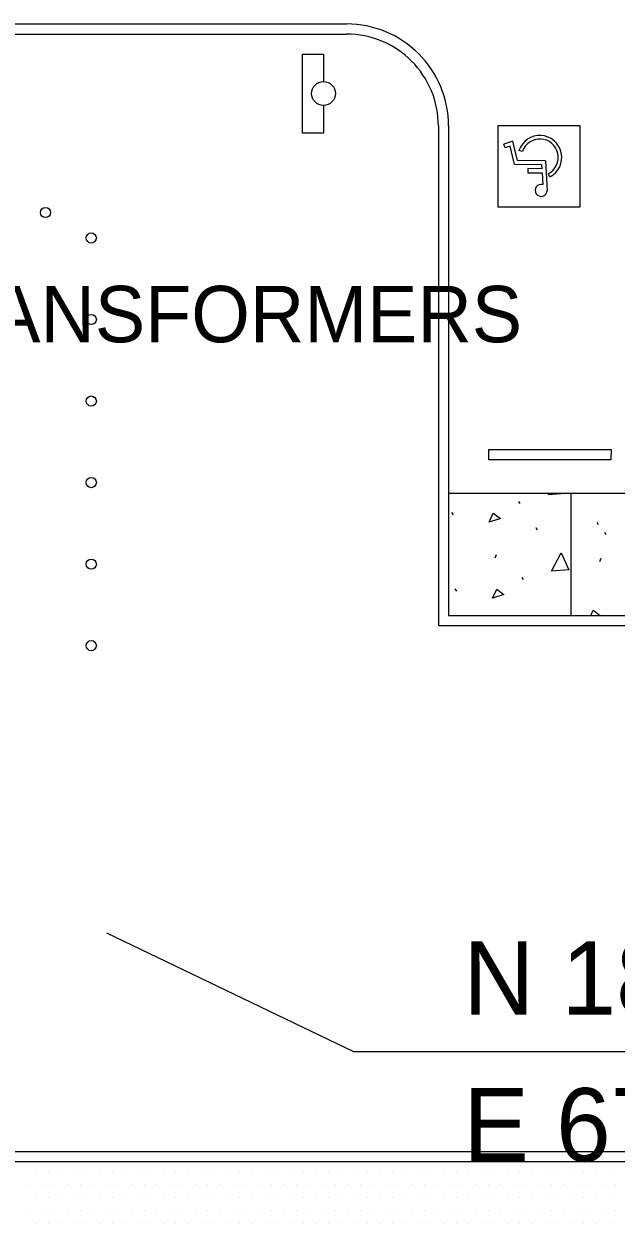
# Model space of a CAD drawing. Extents: x 6712138 to 6712574, y 1869536 to 1870160.
# Drawn here: x 6712356.5 to 6712385.6, y 1869836.3 to 1869895.1 of the extents above; entities that cross this region are included whole.
import ezdxf

# ---------------------------------------------------------------- set-up
doc = ezdxf.new("R2010")
doc.units = 0
for name, color, linetype in [('A-ANNO-TEXT', 7, 'Continuous'), ('A-FLOR-OTLN', 7, 'Continuous'), ('A-FLOR-PATT', 7, 'Continuous'), ('C-PRKG-CONC', 7, 'Continuous'), ('C-SIGN-PARKING', 7, 'Continuous'), ('I-FURN', 7, 'Continuous'), ('I-WALL', 7, 'Continuous'), ('L-SITE-PAVE', 7, 'Continuous')]:
    doc.layers.add(name, color=color, linetype=linetype)

# ---------------------------------------------------------------- blocks, each defined once
blk = doc.blocks.new('G-handy2')
for p, q in [((0, 0), (-0.0002239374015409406, 0.0035868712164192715)), ((-0.000552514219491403, 0.001912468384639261), (-0.0003555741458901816, 0.001537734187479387)), ((0.000380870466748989, 0.0014482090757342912), (0.0002942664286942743, 0.002835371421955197)), ((0.0020983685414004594, 0.0014486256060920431), (0.000380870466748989, 0.0014482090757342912)), ((0.0020984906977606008, 0.0009449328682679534), (0.0020983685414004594, 0.0014486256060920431)), ((0, 0), (0.0033054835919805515, 8.016511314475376e-07)), ((0.0004123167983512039, 0.0009445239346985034), (0.0020984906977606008, 0.0009449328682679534)), ((0.0004419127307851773, 0.0004704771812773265), (0.0004123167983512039, 0.0009445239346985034)), ((0.0004419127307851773, 0.0004704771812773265), (0.0036734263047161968, 0.00047126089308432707)), ((0.0033054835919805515, 8.016511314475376e-07), (0.0038831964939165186, -0.0023286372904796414)), ((0.0036734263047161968, 0.00047126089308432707), (0.004214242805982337, -0.0017094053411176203)), ((0.002744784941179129, -0.0010810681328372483), (0.00314717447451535, -0.0012125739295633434)), ((0.0038831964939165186, -0.0023286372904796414), (0.004932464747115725, -0.0019506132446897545)), ((0.004214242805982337, -0.0017094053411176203), (0.004773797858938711, -0.0015078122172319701)), ((0.004773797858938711, -0.0015078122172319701), (0.004932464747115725, -0.0019506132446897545))]:
    blk.add_line(p, q)
for centre, radius, start, end in [((0.000485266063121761, 0.0035214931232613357), 0.0007122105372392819, 254.44408755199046, 174.7330607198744), ((0.0006632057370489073, -0.0004007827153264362), 0.0026132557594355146, 117.72399317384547, 341.90197805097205), ((0.0006632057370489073, -0.0004007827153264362), 0.002189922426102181, 117.72399317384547, 341.90197805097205)]:
    blk.add_arc(centre, radius, start, end)

msp = doc.modelspace()

# ---------------------------------------------------------------- linework, layer by layer
at = {"layer": 'A-FLOR-OTLN'}
for points in [[(6712251.18275902, 1869839.7810671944), (6712251.18275902, 1869722.3227338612), (6712419.140073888, 1869722.3227338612), (6712419.140073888, 1869718.864400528), (6712468.641092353, 1869718.864400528), (6712468.641092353, 1869839.7810671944)], [(6712251.68275902, 1869839.2810671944), (6712251.68275902, 1869722.8227338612), (6712419.640073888, 1869722.8227338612), (6712419.640073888, 1869719.364400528), (6712468.141092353, 1869719.364400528), (6712468.141092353, 1869839.2810671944)]]:
    msp.add_lwpolyline(points, close=True, dxfattribs=at)
at = {"layer": 'A-FLOR-PATT'}
for p, q in [((6712380.767264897, 1869871.685944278), (6712380.833931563, 1869871.5792776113)), ((6712377.487264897, 1869871.1326109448), (6712377.56059823, 1869871.025944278)), ((6712381.6205982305, 1869870.3992776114), (6712381.693931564, 1869870.2926109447)), ((6712384.607264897, 1869870.6726109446), (6712384.68059823, 1869870.5592776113)), ((6712384.987264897, 1869870.1726109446), (6712385.06059823, 1869870.0659442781)), ((6712379.6205982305, 1869868.9126109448), (6712379.687264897, 1869869.0726109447)), ((6712384.753931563, 1869868.7326109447), (6712384.820598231, 1869868.8926109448)), ((6712377.653931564, 1869867.3926109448), (6712377.727264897, 1869867.2859442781)), ((6712380.933931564, 1869867.945944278), (6712381.007264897, 1869867.845944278)), ((6712357.086960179, 1869838.781746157), (6712357.086960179, 1869838.781746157)), ((6712357.711960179, 1869838.781746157), (6712357.711960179, 1869838.781746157)), ((6712358.336960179, 1869838.781746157), (6712358.336960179, 1869838.781746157)), ((6712358.961960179, 1869838.781746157), (6712358.961960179, 1869838.781746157)), ((6712359.586960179, 1869838.781746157), (6712359.586960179, 1869838.781746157)), ((6712360.211960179, 1869838.781746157), (6712360.211960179, 1869838.781746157)), ((6712360.836960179, 1869838.781746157), (6712360.836960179, 1869838.781746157)), ((6712361.461960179, 1869838.781746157), (6712361.461960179, 1869838.781746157)), ((6712362.086960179, 1869838.781746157), (6712362.086960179, 1869838.781746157)), ((6712362.711960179, 1869838.781746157), (6712362.711960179, 1869838.781746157)), ((6712363.336960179, 1869838.781746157), (6712363.336960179, 1869838.781746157)), ((6712363.961960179, 1869838.781746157), (6712363.961960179, 1869838.781746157)), ((6712364.586960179, 1869838.781746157), (6712364.586960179, 1869838.781746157)), ((6712365.211960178, 1869838.781746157), (6712365.211960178, 1869838.781746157)), ((6712365.836960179, 1869838.781746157), (6712365.836960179, 1869838.781746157)), ((6712366.461960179, 1869838.781746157), (6712366.461960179, 1869838.781746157)), ((6712367.086960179, 1869838.7817461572), (6712367.086960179, 1869838.7817461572)), ((6712367.711960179, 1869838.7817461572), (6712367.711960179, 1869838.7817461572)), ((6712368.336960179, 1869838.781746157), (6712368.336960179, 1869838.781746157)), ((6712368.961960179, 1869838.781746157), (6712368.961960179, 1869838.781746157)), ((6712369.586960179, 1869838.781746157), (6712369.586960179, 1869838.781746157)), ((6712370.211960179, 1869838.781746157), (6712370.211960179, 1869838.781746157)), ((6712370.836960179, 1869838.781746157), (6712370.836960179, 1869838.781746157)), ((6712371.461960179, 1869838.781746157), (6712371.461960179, 1869838.781746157)), ((6712372.086960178, 1869838.781746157), (6712372.086960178, 1869838.781746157)), ((6712372.711960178, 1869838.781746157), (6712372.711960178, 1869838.781746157)), ((6712373.336960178, 1869838.781746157), (6712373.336960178, 1869838.781746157)), ((6712373.961960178, 1869838.781746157), (6712373.961960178, 1869838.781746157)), ((6712374.586960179, 1869838.7817461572), (6712374.586960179, 1869838.7817461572)), ((6712375.211960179, 1869838.781746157), (6712375.211960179, 1869838.781746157)), ((6712375.836960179, 1869838.781746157), (6712375.836960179, 1869838.781746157)), ((6712376.461960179, 1869838.781746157), (6712376.461960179, 1869838.781746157)), ((6712377.086960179, 1869838.781746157), (6712377.086960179, 1869838.781746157)), ((6712377.711960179, 1869838.781746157), (6712377.711960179, 1869838.781746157)), ((6712378.336960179, 1869838.781746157), (6712378.336960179, 1869838.781746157)), ((6712378.961960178, 1869838.781746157), (6712378.961960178, 1869838.781746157)), ((6712379.586960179, 1869838.781746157), (6712379.586960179, 1869838.781746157)), ((6712380.211960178, 1869838.781746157), (6712380.211960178, 1869838.781746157)), ((6712380.836960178, 1869838.781746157), (6712380.836960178, 1869838.781746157)), ((6712381.461960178, 1869838.781746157), (6712381.461960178, 1869838.781746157)), ((6712382.086960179, 1869838.781746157), (6712382.086960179, 1869838.781746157)), ((6712382.711960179, 1869838.7817461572), (6712382.711960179, 1869838.7817461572)), ((6712383.336960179, 1869838.7817461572), (6712383.336960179, 1869838.7817461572)), ((6712383.961960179, 1869838.781746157), (6712383.961960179, 1869838.781746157)), ((6712384.586960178, 1869838.781746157), (6712384.586960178, 1869838.781746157)), ((6712385.211960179, 1869838.781746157), (6712385.211960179, 1869838.781746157)), ((6712356.774460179, 1869838.156746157), (6712356.774460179, 1869838.156746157)), ((6712357.399460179, 1869838.156746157), (6712357.399460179, 1869838.156746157)), ((6712358.024460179, 1869838.156746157), (6712358.024460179, 1869838.156746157)), ((6712358.649460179, 1869838.1567461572), (6712358.649460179, 1869838.1567461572)), ((6712359.274460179, 1869838.156746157), (6712359.274460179, 1869838.156746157)), ((6712359.899460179, 1869838.156746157), (6712359.899460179, 1869838.156746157)), ((6712360.524460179, 1869838.156746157), (6712360.524460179, 1869838.156746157)), ((6712361.149460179, 1869838.1567461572), (6712361.149460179, 1869838.1567461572)), ((6712361.774460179, 1869838.156746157), (6712361.774460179, 1869838.156746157)), ((6712362.399460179, 1869838.156746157), (6712362.399460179, 1869838.156746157)), ((6712363.024460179, 1869838.156746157), (6712363.024460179, 1869838.156746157)), ((6712363.649460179, 1869838.156746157), (6712363.649460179, 1869838.156746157)), ((6712364.27446018, 1869838.1567461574), (6712364.27446018, 1869838.1567461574)), ((6712364.89946018, 1869838.1567461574), (6712364.89946018, 1869838.1567461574)), ((6712365.52446018, 1869838.1567461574), (6712365.52446018, 1869838.1567461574)), ((6712366.14946018, 1869838.1567461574), (6712366.14946018, 1869838.1567461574)), ((6712366.77446018, 1869838.1567461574), (6712366.77446018, 1869838.1567461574)), ((6712367.39946018, 1869838.1567461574), (6712367.39946018, 1869838.1567461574)), ((6712368.02446018, 1869838.1567461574), (6712368.02446018, 1869838.1567461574)), ((6712368.64946018, 1869838.1567461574), (6712368.64946018, 1869838.1567461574)), ((6712369.27446018, 1869838.1567461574), (6712369.27446018, 1869838.1567461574)), ((6712369.899460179, 1869838.1567461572), (6712369.899460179, 1869838.1567461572)), ((6712370.524460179, 1869838.156746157), (6712370.524460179, 1869838.156746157)), ((6712371.149460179, 1869838.156746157), (6712371.149460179, 1869838.156746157)), ((6712371.774460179, 1869838.156746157), (6712371.774460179, 1869838.156746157)), ((6712372.399460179, 1869838.1567461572), (6712372.399460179, 1869838.1567461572)), ((6712373.024460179, 1869838.1567461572), (6712373.024460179, 1869838.1567461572)), ((6712373.649460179, 1869838.156746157), (6712373.649460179, 1869838.156746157)), ((6712374.274460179, 1869838.156746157), (6712374.274460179, 1869838.156746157)), ((6712374.899460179, 1869838.1567461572), (6712374.899460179, 1869838.1567461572)), ((6712375.524460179, 1869838.1567461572), (6712375.524460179, 1869838.1567461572)), ((6712376.149460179, 1869838.1567461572), (6712376.149460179, 1869838.1567461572)), ((6712376.774460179, 1869838.156746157), (6712376.774460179, 1869838.156746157)), ((6712377.399460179, 1869838.1567461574), (6712377.399460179, 1869838.1567461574)), ((6712378.02446018, 1869838.1567461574), (6712378.02446018, 1869838.1567461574)), ((6712378.649460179, 1869838.1567461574), (6712378.649460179, 1869838.1567461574)), ((6712379.27446018, 1869838.1567461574), (6712379.27446018, 1869838.1567461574)), ((6712379.899460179, 1869838.1567461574), (6712379.899460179, 1869838.1567461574)), ((6712380.52446018, 1869838.1567461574), (6712380.52446018, 1869838.1567461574)), ((6712381.149460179, 1869838.1567461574), (6712381.149460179, 1869838.1567461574)), ((6712381.77446018, 1869838.1567461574), (6712381.77446018, 1869838.1567461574)), ((6712382.399460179, 1869838.1567461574), (6712382.399460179, 1869838.1567461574)), ((6712383.024460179, 1869838.1567461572), (6712383.024460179, 1869838.1567461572)), ((6712383.649460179, 1869838.1567461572), (6712383.649460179, 1869838.1567461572)), ((6712384.274460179, 1869838.156746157), (6712384.274460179, 1869838.156746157)), ((6712384.899460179, 1869838.156746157), (6712384.899460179, 1869838.156746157)), ((6712385.524460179, 1869838.156746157), (6712385.524460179, 1869838.156746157)), ((6712357.086960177, 1869837.531746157), (6712357.086960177, 1869837.531746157)), ((6712357.711960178, 1869837.531746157), (6712357.711960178, 1869837.531746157)), ((6712358.336960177, 1869837.531746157), (6712358.336960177, 1869837.531746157)), ((6712358.961960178, 1869837.531746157), (6712358.961960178, 1869837.531746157)), ((6712359.586960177, 1869837.531746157), (6712359.586960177, 1869837.531746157)), ((6712360.211960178, 1869837.531746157), (6712360.211960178, 1869837.531746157)), ((6712360.836960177, 1869837.531746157), (6712360.836960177, 1869837.531746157)), ((6712361.461960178, 1869837.531746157), (6712361.461960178, 1869837.531746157)), ((6712362.086960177, 1869837.531746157), (6712362.086960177, 1869837.531746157)), ((6712362.711960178, 1869837.531746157), (6712362.711960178, 1869837.531746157)), ((6712363.336960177, 1869837.531746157), (6712363.336960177, 1869837.531746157)), ((6712363.961960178, 1869837.531746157), (6712363.961960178, 1869837.531746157)), ((6712364.586960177, 1869837.531746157), (6712364.586960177, 1869837.531746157)), ((6712365.211960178, 1869837.531746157), (6712365.211960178, 1869837.531746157)), ((6712365.836960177, 1869837.531746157), (6712365.836960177, 1869837.531746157)), ((6712366.461960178, 1869837.531746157), (6712366.461960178, 1869837.531746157)), ((6712367.086960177, 1869837.531746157), (6712367.086960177, 1869837.531746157)), ((6712367.711960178, 1869837.531746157), (6712367.711960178, 1869837.531746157)), ((6712368.336960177, 1869837.531746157), (6712368.336960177, 1869837.531746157)), ((6712368.961960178, 1869837.5317461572), (6712368.961960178, 1869837.5317461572)), ((6712369.586960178, 1869837.5317461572), (6712369.586960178, 1869837.5317461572)), ((6712370.211960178, 1869837.5317461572), (6712370.211960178, 1869837.5317461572)), ((6712370.836960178, 1869837.5317461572), (6712370.836960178, 1869837.5317461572)), ((6712371.461960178, 1869837.5317461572), (6712371.461960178, 1869837.5317461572)), ((6712372.086960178, 1869837.5317461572), (6712372.086960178, 1869837.5317461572)), ((6712372.711960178, 1869837.5317461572), (6712372.711960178, 1869837.5317461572)), ((6712373.336960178, 1869837.5317461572), (6712373.336960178, 1869837.5317461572)), ((6712373.961960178, 1869837.5317461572), (6712373.961960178, 1869837.5317461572)), ((6712374.586960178, 1869837.5317461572), (6712374.586960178, 1869837.5317461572)), ((6712375.211960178, 1869837.5317461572), (6712375.211960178, 1869837.5317461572)), ((6712375.836960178, 1869837.5317461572), (6712375.836960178, 1869837.5317461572)), ((6712376.461960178, 1869837.5317461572), (6712376.461960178, 1869837.5317461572)), ((6712377.086960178, 1869837.5317461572), (6712377.086960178, 1869837.5317461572)), ((6712377.711960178, 1869837.5317461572), (6712377.711960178, 1869837.5317461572)), ((6712378.336960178, 1869837.5317461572), (6712378.336960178, 1869837.5317461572)), ((6712378.961960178, 1869837.5317461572), (6712378.961960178, 1869837.5317461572)), ((6712379.586960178, 1869837.531746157), (6712379.586960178, 1869837.531746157)), ((6712380.211960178, 1869837.531746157), (6712380.211960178, 1869837.531746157)), ((6712380.836960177, 1869837.531746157), (6712380.836960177, 1869837.531746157)), ((6712381.461960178, 1869837.531746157), (6712381.461960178, 1869837.531746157)), ((6712382.086960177, 1869837.531746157), (6712382.086960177, 1869837.531746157)), ((6712382.711960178, 1869837.531746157), (6712382.711960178, 1869837.531746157)), ((6712383.336960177, 1869837.531746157), (6712383.336960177, 1869837.531746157)), ((6712383.961960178, 1869837.531746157), (6712383.961960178, 1869837.531746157)), ((6712384.586960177, 1869837.531746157), (6712384.586960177, 1869837.531746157)), ((6712385.211960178, 1869837.531746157), (6712385.211960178, 1869837.531746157)), ((6712356.774460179, 1869836.906746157), (6712356.774460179, 1869836.906746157)), ((6712357.399460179, 1869836.906746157), (6712357.399460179, 1869836.906746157)), ((6712358.024460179, 1869836.9067461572), (6712358.024460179, 1869836.9067461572)), ((6712358.649460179, 1869836.906746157), (6712358.649460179, 1869836.906746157)), ((6712359.274460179, 1869836.906746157), (6712359.274460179, 1869836.906746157)), ((6712359.899460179, 1869836.906746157), (6712359.899460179, 1869836.906746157)), ((6712360.524460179, 1869836.9067461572), (6712360.524460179, 1869836.9067461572)), ((6712361.149460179, 1869836.9067461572), (6712361.149460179, 1869836.9067461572)), ((6712361.774460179, 1869836.9067461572), (6712361.774460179, 1869836.9067461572)), ((6712362.399460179, 1869836.9067461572), (6712362.399460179, 1869836.9067461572)), ((6712363.024460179, 1869836.9067461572), (6712363.024460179, 1869836.9067461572)), ((6712363.649460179, 1869836.9067461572), (6712363.649460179, 1869836.9067461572)), ((6712364.274460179, 1869836.9067461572), (6712364.274460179, 1869836.9067461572)), ((6712364.899460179, 1869836.9067461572), (6712364.899460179, 1869836.9067461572)), ((6712365.524460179, 1869836.9067461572), (6712365.524460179, 1869836.9067461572)), ((6712366.149460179, 1869836.9067461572), (6712366.149460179, 1869836.9067461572)), ((6712366.774460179, 1869836.9067461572), (6712366.774460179, 1869836.9067461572)), ((6712367.399460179, 1869836.9067461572), (6712367.399460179, 1869836.9067461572)), ((6712368.024460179, 1869836.9067461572), (6712368.024460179, 1869836.9067461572)), ((6712368.649460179, 1869836.9067461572), (6712368.649460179, 1869836.9067461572)), ((6712369.274460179, 1869836.9067461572), (6712369.274460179, 1869836.9067461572)), ((6712369.899460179, 1869836.9067461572), (6712369.899460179, 1869836.9067461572)), ((6712370.524460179, 1869836.9067461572), (6712370.524460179, 1869836.9067461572)), ((6712371.149460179, 1869836.9067461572), (6712371.149460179, 1869836.9067461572)), ((6712371.774460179, 1869836.9067461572), (6712371.774460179, 1869836.9067461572)), ((6712372.399460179, 1869836.9067461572), (6712372.399460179, 1869836.9067461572)), ((6712373.024460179, 1869836.9067461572), (6712373.024460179, 1869836.9067461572)), ((6712373.649460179, 1869836.9067461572), (6712373.649460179, 1869836.9067461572)), ((6712374.274460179, 1869836.9067461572), (6712374.274460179, 1869836.9067461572)), ((6712374.899460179, 1869836.9067461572), (6712374.899460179, 1869836.9067461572)), ((6712375.524460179, 1869836.9067461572), (6712375.524460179, 1869836.9067461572)), ((6712376.149460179, 1869836.9067461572), (6712376.149460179, 1869836.9067461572)), ((6712376.774460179, 1869836.9067461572), (6712376.774460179, 1869836.9067461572)), ((6712377.399460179, 1869836.9067461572), (6712377.399460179, 1869836.9067461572)), ((6712378.024460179, 1869836.9067461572), (6712378.024460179, 1869836.9067461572)), ((6712378.649460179, 1869836.9067461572), (6712378.649460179, 1869836.9067461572)), ((6712379.274460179, 1869836.9067461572), (6712379.274460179, 1869836.9067461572)), ((6712379.899460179, 1869836.9067461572), (6712379.899460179, 1869836.9067461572)), ((6712380.524460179, 1869836.9067461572), (6712380.524460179, 1869836.9067461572)), ((6712381.149460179, 1869836.9067461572), (6712381.149460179, 1869836.9067461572)), ((6712381.774460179, 1869836.9067461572), (6712381.774460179, 1869836.9067461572)), ((6712382.399460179, 1869836.9067461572), (6712382.399460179, 1869836.9067461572)), ((6712383.024460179, 1869836.9067461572), (6712383.024460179, 1869836.9067461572)), ((6712383.649460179, 1869836.9067461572), (6712383.649460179, 1869836.9067461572)), ((6712384.274460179, 1869836.9067461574), (6712384.274460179, 1869836.9067461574)), ((6712384.899460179, 1869836.9067461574), (6712384.899460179, 1869836.9067461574)), ((6712385.524460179, 1869836.9067461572), (6712385.524460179, 1869836.9067461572)), ((6712357.086960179, 1869836.281746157), (6712357.086960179, 1869836.281746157)), ((6712357.711960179, 1869836.281746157), (6712357.711960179, 1869836.281746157)), ((6712358.336960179, 1869836.281746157), (6712358.336960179, 1869836.281746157)), ((6712358.961960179, 1869836.281746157), (6712358.961960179, 1869836.281746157)), ((6712359.586960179, 1869836.281746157), (6712359.586960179, 1869836.281746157)), ((6712360.211960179, 1869836.281746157), (6712360.211960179, 1869836.281746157)), ((6712360.836960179, 1869836.2817461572), (6712360.836960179, 1869836.2817461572)), ((6712361.461960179, 1869836.2817461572), (6712361.461960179, 1869836.2817461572)), ((6712362.086960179, 1869836.2817461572), (6712362.086960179, 1869836.2817461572)), ((6712362.711960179, 1869836.281746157), (6712362.711960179, 1869836.281746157)), ((6712363.336960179, 1869836.2817461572), (6712363.336960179, 1869836.2817461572)), ((6712363.961960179, 1869836.2817461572), (6712363.961960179, 1869836.2817461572)), ((6712364.586960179, 1869836.2817461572), (6712364.586960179, 1869836.2817461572)), ((6712365.211960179, 1869836.2817461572), (6712365.211960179, 1869836.2817461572)), ((6712365.836960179, 1869836.281746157), (6712365.836960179, 1869836.281746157)), ((6712366.461960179, 1869836.2817461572), (6712366.461960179, 1869836.2817461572)), ((6712367.086960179, 1869836.2817461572), (6712367.086960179, 1869836.2817461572)), ((6712367.711960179, 1869836.2817461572), (6712367.711960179, 1869836.2817461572)), ((6712368.336960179, 1869836.2817461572), (6712368.336960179, 1869836.2817461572)), ((6712368.961960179, 1869836.2817461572), (6712368.961960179, 1869836.2817461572)), ((6712369.586960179, 1869836.2817461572), (6712369.586960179, 1869836.2817461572)), ((6712370.211960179, 1869836.2817461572), (6712370.211960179, 1869836.2817461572)), ((6712370.836960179, 1869836.2817461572), (6712370.836960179, 1869836.2817461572)), ((6712371.461960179, 1869836.2817461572), (6712371.461960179, 1869836.2817461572)), ((6712372.086960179, 1869836.2817461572), (6712372.086960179, 1869836.2817461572)), ((6712372.711960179, 1869836.2817461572), (6712372.711960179, 1869836.2817461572)), ((6712373.336960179, 1869836.2817461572), (6712373.336960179, 1869836.2817461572)), ((6712373.961960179, 1869836.2817461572), (6712373.961960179, 1869836.2817461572)), ((6712374.586960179, 1869836.2817461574), (6712374.586960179, 1869836.2817461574)), ((6712375.211960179, 1869836.2817461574), (6712375.211960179, 1869836.2817461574)), ((6712375.836960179, 1869836.2817461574), (6712375.836960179, 1869836.2817461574)), ((6712376.461960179, 1869836.2817461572), (6712376.461960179, 1869836.2817461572)), ((6712377.086960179, 1869836.2817461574), (6712377.086960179, 1869836.2817461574)), ((6712377.711960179, 1869836.2817461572), (6712377.711960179, 1869836.2817461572)), ((6712378.336960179, 1869836.281746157), (6712378.336960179, 1869836.281746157)), ((6712378.961960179, 1869836.281746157), (6712378.961960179, 1869836.281746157)), ((6712379.586960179, 1869836.281746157), (6712379.586960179, 1869836.281746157)), ((6712380.211960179, 1869836.281746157), (6712380.211960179, 1869836.281746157)), ((6712380.836960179, 1869836.281746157), (6712380.836960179, 1869836.281746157)), ((6712381.461960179, 1869836.281746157), (6712381.461960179, 1869836.281746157)), ((6712382.086960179, 1869836.2817461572), (6712382.086960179, 1869836.2817461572)), ((6712382.711960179, 1869836.281746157), (6712382.711960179, 1869836.281746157)), ((6712383.336960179, 1869836.281746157), (6712383.336960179, 1869836.281746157)), ((6712383.961960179, 1869836.281746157), (6712383.961960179, 1869836.281746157)), ((6712384.586960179, 1869836.281746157), (6712384.586960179, 1869836.281746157)), ((6712385.211960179, 1869836.281746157), (6712385.211960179, 1869836.281746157))]:
    msp.add_line(p, q, dxfattribs=at)
for points in [[(6712382.22059823, 1869871.9992776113), (6712382.269963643, 1869872.0924461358)], [(6712383.051728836, 1869872.0924461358), (6712383.06059823, 1869872.0726109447), (6712382.240598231, 1869871.9992776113)], [(6712379.327264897, 1869870.6726109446), (6712379.533931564, 1869871.1126109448), (6712379.887264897, 1869870.845944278), (6712379.327264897, 1869870.6726109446)], [(6712377.339958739, 1869869.787374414), (6712377.34059823, 1869869.7859442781), (6712377.339958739, 1869869.785887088)], [(6712382.387264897, 1869868.265944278), (6712382.860598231, 1869869.1592776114), (6712383.233931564, 1869868.3326109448), (6712382.407264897, 1869868.265944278)], [(6712379.493931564, 1869866.9392776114), (6712379.707264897, 1869867.3726109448), (6712380.053931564, 1869867.1126109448), (6712379.493931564, 1869866.9392776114)], [(6712384.32153092, 1869866.092446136), (6712384.44059823, 1869866.345944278), (6712384.785095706, 1869866.092446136)]]:
    msp.add_lwpolyline(points, dxfattribs=at)
at = {"layer": 'C-PRKG-CONC'}
for p, q in [((6712335.29716914, 1869895.1070740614), (6712372.340038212, 1869895.1070740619)), ((6712335.29716914, 1869894.6070740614), (6712372.340038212, 1869894.6070740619)), ((6712376.840038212, 1869890.1070542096), (6712376.839930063, 1869865.592446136)), ((6712377.340038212, 1869890.107052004), (6712377.3399322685, 1869866.0924461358)), ((6712379.307576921, 1869873.7279073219), (6712379.310805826, 1869874.2279073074)), ((6712379.310805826, 1869874.2279073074), (6712385.310930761, 1869874.2278808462)), ((6712385.310930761, 1869874.2278808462), (6712385.307701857, 1869873.727880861)), ((6712385.307701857, 1869873.7278808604), (6712379.307576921, 1869873.7279073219)), ((6712377.339958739, 1869872.0924461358), (6712459.339968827, 1869872.0924461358)), ((6712377.3399322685, 1869866.0924461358), (6712459.339930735, 1869866.0924461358)), ((6712376.839930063, 1869865.592446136), (6712459.839928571, 1869865.5924461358))]:
    msp.add_line(p, q, dxfattribs=at)
msp.add_lwpolyline([(6712379.7755375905, 1869890.1186332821), (6712383.775537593, 1869890.1186332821), (6712383.775537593, 1869886.1186332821), (6712379.775537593, 1869886.1186332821)], close=True, dxfattribs=at)
for radius, start, end in [(5, 359.99974723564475, 89.99999999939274), (4.5, 359.9997472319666, 90)]:
    msp.add_arc((6712372.340038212, 1869890.1070740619), radius, start, end, dxfattribs=at)
at = {"layer": 'C-SIGN-PARKING'}
msp.add_lwpolyline([(6712371.201187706, 1869891.1089582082), (6712371.201187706, 1869889.7565326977), (6712370.167438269, 1869889.7565326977), (6712370.167438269, 1869893.6330930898), (6712371.201187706, 1869893.6330930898), (6712371.201187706, 1869892.2806675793)], dxfattribs=at)
msp.add_circle((6712371.201187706, 1869891.6948128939), 0.5858546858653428, dxfattribs=at)
at = {"layer": 'I-FURN'}
for centre, radius in [((6712357.557285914, 1869885.8574032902), 0.249999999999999), ((6712359.807285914, 1869884.6074032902), 0.25), ((6712359.807285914, 1869880.6074032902), 0.25), ((6712359.807285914, 1869876.6074032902), 0.25), ((6712359.807285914, 1869872.6074032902), 0.25), ((6712359.807285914, 1869868.6074032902), 0.25), ((6712359.807285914, 1869864.6074032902), 0.25)]:
    msp.add_circle(centre, radius, dxfattribs=at)
at = {"layer": 'I-WALL'}
for points in [[(6712360.558394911, 1869850.5253812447), (6712372.668248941, 1869844.7007855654)], [(6712372.668248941, 1869844.7007855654), (6712414.691870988, 1869844.7007855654)]]:
    msp.add_lwpolyline(points, dxfattribs=at)
at = {"layer": 'L-SITE-PAVE'}
msp.add_line((6712383.339958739, 1869872.0924461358), (6712383.339958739, 1869866.092446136), dxfattribs=at)

# ---------------------------------------------------------------- block references
at = {"layer": 'C-PRKG-CONC', "xscale": 412.3229143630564, "yscale": 412.3229143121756, "rotation": 179.73949444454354}
msp.add_blockref('G-handy2', (6712382.088809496, 1869888.3955576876), dxfattribs=at)

# ---------------------------------------------------------------- texts
at = {"layer": 'A-ANNO-TEXT'}
msp.add_text('TRANSFORMERS', height=2.7661863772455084, dxfattribs=at).set_placement((6712349.916335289, 1869879.4920964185))
msp.add_text('TRANSFORMERS', height=2.7661863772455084, dxfattribs=at).set_placement((6712349.916335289, 1869879.4920964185))
at = {"layer": 'I-WALL'}
for s, p in [('N 1869850.53', (6712378.068248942, 1869846.5007855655)), ('E 6712360.56', (6712378.068248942, 1869839.3007855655))]:
    msp.add_text(s, height=3.6, dxfattribs=at).set_placement(p)

doc.saveas('drawing.dxf')
